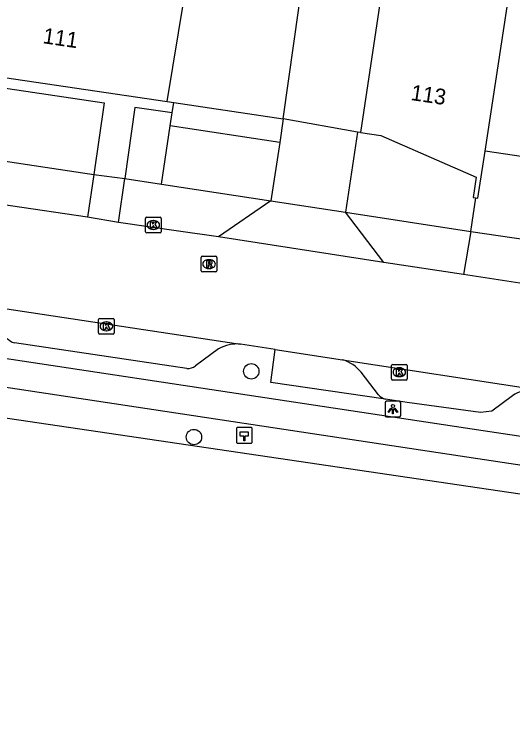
# Model space of a CAD drawing. Extents: x 163010 to 163853, y 382793 to 383982.
# Drawn here: x 163550.15 to 163581.89, y 382793.19 to 382839.26 of the extents above; entities that cross this region are included whole.
import ezdxf

# ---------------------------------------------------------------- set-up
doc = ezdxf.new("R2010")
doc.units = 0
for name, color, linetype in [('IMGEO_Boom', 7, 'Continuous'), ('IMGEO_Fietspad_open', 7, 'Continuous'), ('IMGEO_Hectometerpaal', 7, 'Continuous'), ('IMGEO_Kolk', 7, 'Continuous'), ('IMGEO_Lichtpunt', 7, 'Continuous'), ('IMGEO_Pand', 7, 'Continuous'), ('IMGEO_Pand_nummerreeks', 7, 'Continuous'), ('IMGEO_Parkeervlak_open', 7, 'Continuous'), ('IMGEO_Rijbaan_lokaal_open', 7, 'Continuous'), ('IMGEO_Rioolput', 7, 'Continuous'), ('IMGEO_Voetpad_open', 7, 'Continuous'), ('IMGEO_Waterloop', 7, 'Continuous')]:
    doc.layers.add(name, color=color, linetype=linetype)

msp = doc.modelspace()

# ---------------------------------------------------------------- linework, layer by layer
at = {"layer": 'IMGEO_Boom'}
for centre in [(163565.243, 382816.526), (163561.589, 382812.338)]:
    msp.add_circle(centre, 0.489, dxfattribs=at)
at = {"layer": 'IMGEO_Fietspad_open'}
for points in [[(163686.181, 382796.847), (163580.024, 382812.745), (163535.568, 382819.448), (163509.609, 382823.407)], [(163509.094, 382821.64), (163535.397, 382817.662), (163579.683, 382810.971), (163685.894, 382795.009), (163685.894, 382795.009)]]:
    msp.add_lwpolyline(points, dxfattribs=at)
at = {"layer": 'IMGEO_Hectometerpaal'}
for p, q in [((163564.299, 382812.864), (163564.299, 382812.023)), ((163564.299, 382812.864), (163564.299, 382812.023)), ((163565.215, 382812.948), (163564.374, 382812.948)), ((163565.215, 382812.948), (163564.374, 382812.948)), ((163565.299, 382812.032), (163565.299, 382812.873)), ((163565.299, 382812.032), (163565.299, 382812.873)), ((163564.383, 382811.948), (163565.224, 382811.948)), ((163564.383, 382811.948), (163565.224, 382811.948))]:
    msp.add_line(p, q, dxfattribs=at)
msp.add_lwpolyline([(163564.824, 382812.092), (163564.764, 382812.092), (163564.764, 382812.397), (163564.544, 382812.397), (163564.544, 382812.666), (163565.044, 382812.666), (163565.044, 382812.397), (163564.824, 382812.397), (163564.824, 382812.092)], dxfattribs=at)
for centre, start, end in [((163564.377, 382812.87), 92.4484, 184.2845), ((163564.377, 382812.87), 92.4484, 184.2845), ((163565.221, 382812.87), 2.4484, 94.2845), ((163565.221, 382812.87), 2.4484, 94.2845), ((163564.377, 382812.026), 182.4484, 274.2845), ((163564.377, 382812.026), 182.4484, 274.2845), ((163565.221, 382812.026), 272.4484, 4.2845), ((163565.221, 382812.026), 272.4484, 4.2845)]:
    msp.add_arc(centre, 0.0779, start, end, dxfattribs=at)
at = {"layer": 'IMGEO_Kolk'}
for p, q in [((163558.501, 382825.419), (163558.501, 382826.271)), ((163558.576, 382826.345), (163559.428, 382826.345)), ((163558.989, 382826.125), (163559.014, 382826.125)), ((163559.502, 382826.271), (163559.502, 382825.419)), ((163559.012, 382825.565), (163558.987, 382825.565)), ((163559.428, 382825.345), (163558.576, 382825.345)), ((163555.508, 382818.968), (163555.508, 382819.82)), ((163555.583, 382819.894), (163556.435, 382819.894)), ((163555.996, 382819.674), (163556.021, 382819.674)), ((163556.509, 382819.82), (163556.509, 382818.968)), ((163556.019, 382819.114), (163555.994, 382819.114)), ((163556.435, 382818.894), (163555.583, 382818.894)), ((163574.179, 382816.043), (163574.179, 382816.895)), ((163574.254, 382816.969), (163575.106, 382816.969)), ((163574.667, 382816.749), (163574.692, 382816.749)), ((163575.18, 382816.895), (163575.18, 382816.043)), ((163575.106, 382815.969), (163574.254, 382815.969)), ((163574.69, 382816.189), (163574.665, 382816.189))]:
    msp.add_line(p, q, dxfattribs=at)
for points in [[(163558.501, 382825.419), (163558.501, 382826.271)], [(163558.576, 382826.345), (163559.428, 382826.345)], [(163558.822, 382826.045), (163558.945, 382826.045), (163558.945, 382825.894), (163559.075, 382826.045), (163559.239, 382826.045), (163559.093, 382825.894), (163559.246, 382825.645), (163559.094, 382825.645), (163559.009, 382825.809), (163558.945, 382825.742), (163558.945, 382825.645), (163558.822, 382825.645), (163558.822, 382826.045)], [(163559.502, 382826.271), (163559.502, 382825.419)], [(163559.428, 382825.345), (163558.576, 382825.345)], [(163555.508, 382818.968), (163555.508, 382819.82)], [(163555.583, 382819.894), (163556.435, 382819.894)], [(163555.829, 382819.594), (163555.952, 382819.594), (163555.952, 382819.443), (163556.082, 382819.594), (163556.246, 382819.594), (163556.1, 382819.443), (163556.253, 382819.194), (163556.101, 382819.194), (163556.016, 382819.358), (163555.952, 382819.291), (163555.952, 382819.194), (163555.829, 382819.194), (163555.829, 382819.594)], [(163556.509, 382819.82), (163556.509, 382818.968)], [(163556.435, 382818.894), (163555.583, 382818.894)], [(163574.179, 382816.043), (163574.179, 382816.895)], [(163574.254, 382816.969), (163575.106, 382816.969)], [(163575.18, 382816.895), (163575.18, 382816.043)], [(163574.5, 382816.669), (163574.623, 382816.669), (163574.623, 382816.518), (163574.753, 382816.669), (163574.917, 382816.669), (163574.771, 382816.518), (163574.924, 382816.269), (163574.772, 382816.269), (163574.687, 382816.433), (163574.623, 382816.366), (163574.623, 382816.269), (163574.5, 382816.269), (163574.5, 382816.669)], [(163575.106, 382815.969), (163574.254, 382815.969)]]:
    msp.add_lwpolyline(points, dxfattribs=at)
for centre, start, end in [((163558.578, 382826.269), 91.552, 178.448), ((163558.578, 382826.269), 91.552, 178.448), ((163559.426, 382826.269), 1.552, 88.448), ((163559.426, 382826.269), 1.552, 88.448), ((163558.578, 382825.421), 181.552, 268.448), ((163558.578, 382825.421), 181.552, 268.448), ((163559.426, 382825.421), 271.552, 358.448), ((163559.426, 382825.421), 271.552, 358.448), ((163555.585, 382819.818), 91.552, 178.448), ((163555.585, 382819.818), 91.552, 178.448), ((163556.433, 382819.818), 1.552, 88.448), ((163556.433, 382819.818), 1.552, 88.448), ((163555.585, 382818.97), 181.552, 268.448), ((163555.585, 382818.97), 181.552, 268.448), ((163556.433, 382818.97), 271.552, 358.448), ((163556.433, 382818.97), 271.552, 358.448), ((163574.256, 382816.893), 91.552, 178.448), ((163574.256, 382816.893), 91.552, 178.448), ((163575.104, 382816.893), 1.552, 88.448), ((163575.104, 382816.893), 1.552, 88.448), ((163574.256, 382816.045), 181.552, 268.448), ((163574.256, 382816.045), 181.552, 268.448), ((163575.104, 382816.045), 271.552, 358.448), ((163575.104, 382816.045), 271.552, 358.448)]:
    msp.add_arc(centre, 0.0765, start, end, dxfattribs=at)
for centre, major_axis, ratio, start_param, end_param in [((163558.988, 382825.845), (-0.387, 0.002), 0.722429, 4.712389, 7.853982), ((163559.013, 382825.845), (-0.39, 0.002), 0.717154, 1.570796, 4.712389), ((163555.995, 382819.394), (-0.387, 0.002), 0.722429, 4.712389, 7.853982), ((163556.02, 382819.394), (-0.39, 0.002), 0.717154, 1.570796, 4.712389), ((163574.666, 382816.469), (-0.387, 0.002), 0.722429, 4.712389, 7.853982), ((163574.691, 382816.469), (-0.39, 0.002), 0.717154, 1.570796, 4.712389)]:
    msp.add_ellipse(centre, major_axis=major_axis, ratio=ratio, start_param=start_param, end_param=end_param, dxfattribs=at)
at = {"layer": 'IMGEO_Lichtpunt'}
for p, q in [((163573.77, 382814.521), (163573.77, 382813.714)), ((163573.77, 382814.521), (163573.77, 382813.714)), ((163574.672, 382814.616), (163573.864, 382814.616)), ((163574.672, 382814.616), (163573.864, 382814.616)), ((163574.766, 382813.714), (163574.766, 382814.521)), ((163574.766, 382813.714), (163574.766, 382814.521)), ((163573.864, 382813.62), (163574.672, 382813.62)), ((163573.864, 382813.62), (163574.672, 382813.62))]:
    msp.add_line(p, q, dxfattribs=at)
for points in [[(163574.144, 382814.185), (163574.183, 382814.157), (163573.995, 382813.895), (163573.957, 382813.922), (163574.144, 382814.185)], [(163574.246, 382814.137), (163574.293, 382814.137), (163574.293, 382813.815), (163574.246, 382813.815), (163574.246, 382814.137)], [(163574.356, 382814.157), (163574.394, 382814.184), (163574.581, 382813.922), (163574.542, 382813.894), (163574.356, 382814.157)]]:
    msp.add_lwpolyline(points, dxfattribs=at)
msp.add_circle((163574.269, 382814.319), 0.0994, dxfattribs=at)
for centre, start, end in [((163573.864, 382814.521), 90, 180), ((163573.864, 382814.521), 90, 180), ((163574.672, 382814.521), 0, 90), ((163574.672, 382814.521), 0, 90), ((163573.864, 382813.714), 180, 270), ((163573.864, 382813.714), 180, 270), ((163574.672, 382813.714), 270, 0), ((163574.672, 382813.714), 270, 360)]:
    msp.add_arc(centre, 0.0946, start, end, dxfattribs=at)
at = {"layer": 'IMGEO_Pand'}
for points in [[(163559.875, 382833.708), (163570.11, 382895.617)], [(163580.14, 382830.556), (163589.621, 382892.728), (163589.252, 382892.786)], [(163567.268, 382832.611), (163568.61, 382842.083), (163565.741, 382842.516), (163565.583, 382841.472), (163561.492, 382842.089), (163563.84, 382857.653), (163568.311, 382856.979), (163569.202, 382862.922), (163576.698, 382861.797), (163572.213, 382831.739)], [(163545.356, 382835.858), (163545.604, 382835.822), (163559.875, 382833.708)], [(163559.875, 382833.708), (163560.299, 382833.645)], [(163560.299, 382833.645), (163567.268, 382832.611)], [(163572.213, 382831.739), (163573.49, 382831.548), (163579.586, 382828.891), (163579.393, 382827.605), (163579.558, 382827.581)], [(163579.558, 382827.581), (163579.683, 382827.562), (163580.14, 382830.556)], [(163588.963, 382829.239), (163583.75, 382830.017), (163580.14, 382830.556)]]:
    msp.add_lwpolyline(points, dxfattribs=at)
at = {"layer": 'IMGEO_Parkeervlak_open'}
for points in [[(163561.128, 382816.699), (163550.148, 382818.343)], [(163563.158, 382817.955), (163561.697, 382816.867)], [(163581.894, 382814.961), (163580.573, 382813.998), (163579.862, 382813.9), (163575.171, 382814.55), (163573.8, 382814.748)]]:
    msp.add_lwpolyline(points, dxfattribs=at)
for centre, radius, start, end in [((163550.501, 382819.51), 1.219, 225.5897, 253.1592), ((163564.304, 382816.015), 2.254, 83.81, 120.5654), ((163561.133, 382817.729), 1.03, 269.7135, 303.1855), ((163583.232, 382813.122), 2.275, 88.9503, 126.0412)]:
    msp.add_arc(centre, radius, start, end, dxfattribs=at)
at = {"layer": 'IMGEO_Rijbaan_lokaal_open'}
for points in [[(163554.805, 382826.351), (163549.901, 382827.064), (163544.056, 382827.913)], [(163556.788, 382825.999), (163554.805, 382826.351)], [(163563.153, 382825.089), (163560.598, 382825.454), (163556.788, 382825.999)], [(163573.688, 382823.453), (163563.153, 382825.089)], [(163578.766, 382822.69), (163573.688, 382823.453)], [(163586.272, 382821.533), (163584.294, 382821.838), (163578.766, 382822.69)], [(163547.53, 382820.816), (163564.547, 382818.255)], [(163566.771, 382817.917), (163564.547, 382818.255)], [(163566.771, 382817.917), (163571.05, 382817.267)], [(163571.05, 382817.267), (163583.274, 382815.396)]]:
    msp.add_lwpolyline(points, dxfattribs=at)
at = {"layer": 'IMGEO_Rioolput'}
for p, q in [((163562.051, 382822.93), (163562.051, 382823.782)), ((163562.126, 382823.856), (163562.978, 382823.856)), ((163563.052, 382823.782), (163563.052, 382822.93)), ((163562.539, 382823.636), (163562.564, 382823.636)), ((163562.978, 382822.856), (163562.126, 382822.856)), ((163562.562, 382823.076), (163562.537, 382823.076))]:
    msp.add_line(p, q, dxfattribs=at)
for points in [[(163562.051, 382822.93), (163562.051, 382823.782)], [(163562.126, 382823.856), (163562.978, 382823.856)], [(163563.052, 382823.782), (163563.052, 382822.93)], [(163562.64, 382823.554), (163562.388, 382823.556), (163562.388, 382823.156)], [(163562.388, 382823.156), (163562.512, 382823.156), (163562.512, 382823.318), (163562.523, 382823.318)], [(163562.566, 382823.475), (163562.512, 382823.475), (163562.512, 382823.394)], [(163562.512, 382823.394), (163562.564, 382823.394)], [(163562.57, 382823.289), (163562.641, 382823.156), (163562.781, 382823.156), (163562.716, 382823.282)], [(163562.978, 382822.856), (163562.126, 382822.856)]]:
    msp.add_lwpolyline(points, dxfattribs=at)
for centre, radius, start, end in [((163562.128, 382823.78), 0.0765, 91.552, 178.448), ((163562.128, 382823.78), 0.0765, 91.552, 178.448), ((163562.976, 382823.78), 0.0765, 1.552, 88.448), ((163562.976, 382823.78), 0.0765, 1.552, 88.448), ((163562.522, 382823.265), 0.0533, 26.0293, 88.6989), ((163562.548, 382823.583), 0.19, 274.7715, 282.9687), ((163562.572, 382823.379), 0.0964, 77.0061, 93.1865), ((163562.586, 382823.436), 0.0378, 276.6634, 79.6772), ((163562.639, 382823.444), 0.109, 350.3612, 89.416), ((163562.637, 382823.444), 0.112, 277.5842, 350.9817), ((163562.621, 382823.229), 0.108, 29.5134, 73.7905), ((163562.128, 382822.932), 0.0765, 181.552, 268.448), ((163562.128, 382822.932), 0.0765, 181.552, 268.448), ((163562.976, 382822.932), 0.0765, 271.552, 358.448), ((163562.976, 382822.932), 0.0765, 271.552, 358.448)]:
    msp.add_arc(centre, radius, start, end, dxfattribs=at)
for centre, major_axis, ratio, start_param, end_param in [((163562.538, 382823.356), (-0.387, 0.002), 0.722429, 4.712389, 7.853982), ((163562.563, 382823.356), (-0.39, 0.002), 0.717154, 1.570796, 4.712389)]:
    msp.add_ellipse(centre, major_axis=major_axis, ratio=ratio, start_param=start_param, end_param=end_param, dxfattribs=at)
at = {"layer": 'IMGEO_Voetpad_open'}
for points in [[(163545.133, 382835.224), (163555.872, 382833.621), (163555.214, 382829.064)], [(163560.202, 382832.998), (163557.812, 382833.342), (163557.176, 382828.801)], [(163560.202, 382832.998), (163560.299, 382833.645)], [(163560.077, 382832.163), (163560.202, 382832.998)], [(163567.268, 382832.611), (163567.059, 382831.096)], [(163572.018, 382831.773), (163567.268, 382832.611)], [(163559.521, 382828.445), (163560.077, 382832.163)], [(163567.059, 382831.096), (163560.077, 382832.163)], [(163572.018, 382831.773), (163571.245, 382826.669)], [(163572.213, 382831.739), (163572.018, 382831.773)], [(163567.059, 382831.096), (163566.478, 382827.389)], [(163544.475, 382830.676), (163555.214, 382829.064)], [(163555.214, 382829.064), (163554.805, 382826.351)], [(163555.214, 382829.064), (163557.176, 382828.801)], [(163556.788, 382825.999), (163557.176, 382828.801)], [(163557.176, 382828.801), (163559.521, 382828.445)], [(163559.521, 382828.445), (163566.478, 382827.389)], [(163566.478, 382827.389), (163563.153, 382825.089)], [(163566.478, 382827.389), (163571.245, 382826.669)], [(163579.241, 382825.44), (163579.558, 382827.581)], [(163571.245, 382826.669), (163579.241, 382825.44)], [(163573.688, 382823.453), (163571.245, 382826.669)], [(163579.241, 382825.44), (163578.766, 382822.69)], [(163579.241, 382825.44), (163586.647, 382824.35)], [(163573.8, 382814.748), (163566.484, 382815.807), (163566.771, 382817.917)], [(163573.342, 382815.022), (163572.245, 382816.467)]]:
    msp.add_lwpolyline(points, dxfattribs=at)
for centre, radius, start, end in [((163570.389, 382814.987), 2.374, 38.568, 73.8308), ((163574.147, 382815.848), 1.153, 225.7333, 252.4865)]:
    msp.add_arc(centre, radius, start, end, dxfattribs=at)
at = {"layer": 'IMGEO_Waterloop'}
msp.add_lwpolyline([(163685.611, 382793.195), (163685.611, 382793.195), (163685.451, 382793.218), (163644.684, 382799.5), (163532.552, 382816.044), (163514.398, 382818.897), (163500, 382817.915), (163490.933, 382817.132), (163485.145, 382816.814), (163483.656, 382816.879), (163421.963, 382825.134), (163407.316, 382827.646), (163347.839, 382838.095)], dxfattribs=at)

# ---------------------------------------------------------------- texts
at = {"layer": 'IMGEO_Pand_nummerreeks'}
for s, rotation, p in [('111', 351.5775, (163551.914, 382837.435)), ('113', 351.5088, (163575.366, 382833.816))]:
    msp.add_text(s, height=1, rotation=rotation, dxfattribs=at).set_placement(p)

doc.saveas('drawing.dxf')
